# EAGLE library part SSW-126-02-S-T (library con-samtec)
THROUGH-HOLE .025" SQ POST SOCKET Source: Samtec SSW.pdf
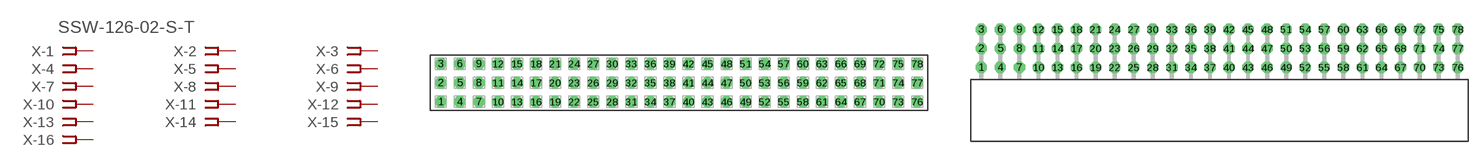
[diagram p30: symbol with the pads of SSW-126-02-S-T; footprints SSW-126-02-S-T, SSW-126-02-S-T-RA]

Designator prefix X; gates -1=FPINV -2=FPIN -3=FPIN -4=FPIN -5=FPIN -6=FPIN -7=FPIN -8=FPIN -9=FPIN -10=FPIN -11=FPIN -12=FPIN -13=FPIN -14=FPIN -15=FPIN -16=FPIN -17=FPIN -18=FPIN -19=FPIN -20=FPIN -21=FPIN -22=FPIN -23=FPIN -24=FPIN -25=FPIN -26=FPIN -27=FPIN -28=FPIN -29=FPIN -30=FPIN -31=FPIN -32=FPIN -33=FPIN -34=FPIN -35=FPIN -36=FPIN -37=FPIN -38=FPIN -39=FPIN -40=FPIN -41=FPIN -42=FPIN -43=FPIN -44=FPIN -45=FPIN -46=FPIN -47=FPIN -48=FPIN -49=FPIN -50=FPIN -51=FPIN -52=FPIN -53=FPIN -54=FPIN -55=FPIN -56=FPIN -57=FPIN -58=FPIN -59=FPIN -60=FPIN -61=FPIN -62=FPIN -63=FPIN -64=FPIN -65=FPIN -66=FPIN -67=FPIN -68=FPIN -69=FPIN -70=FPIN -71=FPIN -72=FPIN -73=FPIN -74=FPIN -75=FPIN -76=FPIN -77=FPIN -78=FPIN

## SSW-126-02-S-T (MPN: SSW-126-02-S-T; OC_FARNELL: unknown; OC_NEWARK: 82P9576)  [SSW-126-02-S-T]
1  -1:1  pas
2  -2:1  pas
3  -3:1  pas
4  -4:1  pas
5  -5:1  pas
6  -6:1  pas
7  -7:1  pas
8  -8:1  pas
9  -9:1  pas
10  -10:1  pas
11  -11:1  pas
12  -12:1  pas
13  -13:1  pas
14  -14:1  pas
15  -15:1  pas
16  -16:1  pas
17  -17:1  pas
18  -18:1  pas
19  -19:1  pas
20  -20:1  pas
21  -21:1  pas
22  -22:1  pas
23  -23:1  pas
24  -24:1  pas
25  -25:1  pas
26  -26:1  pas
27  -27:1  pas
28  -28:1  pas
29  -29:1  pas
30  -30:1  pas
31  -31:1  pas
32  -32:1  pas
33  -33:1  pas
34  -34:1  pas
35  -35:1  pas
36  -36:1  pas
37  -37:1  pas
38  -38:1  pas
39  -39:1  pas
40  -40:1  pas
41  -41:1  pas
42  -42:1  pas
43  -43:1  pas
44  -44:1  pas
45  -45:1  pas
46  -46:1  pas
47  -47:1  pas
48  -48:1  pas
49  -49:1  pas
50  -50:1  pas
51  -51:1  pas
52  -52:1  pas
53  -53:1  pas
54  -54:1  pas
55  -55:1  pas
56  -56:1  pas
57  -57:1  pas
58  -58:1  pas
59  -59:1  pas
60  -60:1  pas
61  -61:1  pas
62  -62:1  pas
63  -63:1  pas
64  -64:1  pas
65  -65:1  pas
66  -66:1  pas
67  -67:1  pas
68  -68:1  pas
69  -69:1  pas
70  -70:1  pas
71  -71:1  pas
72  -72:1  pas
73  -73:1  pas
74  -74:1  pas
75  -75:1  pas
76  -76:1  pas
77  -77:1  pas
78  -78:1  pas

## SSW-126-02-S-TRA (MPN: SSW-126-02-S-T-RA; OC_FARNELL: unknown; OC_NEWARK: 82P9577)  [SSW-126-02-S-T-RA]
Pads as for SSW-126-02-S-T

## Footprint SSW-126-02-S-T (pad centres in mm)
THROUGH-HOLE .025" SQ POST SOCKET Source: Samtec SSW.pdf
drill 1 pad 1.5 octagon: 1 -31.75,-2.54; 2 -31.75,0; 3 -31.75,2.54; 4 -29.21,-2.54; 5 -29.21,0; 6 -29.21,2.54; 7 -26.67,-2.54; 8 -26.67,0; 9 -26.67,2.54; 10 -24.13,-2.54; 11 -24.13,0; 12 -24.13,2.54; 13 -21.59,-2.54; 14 -21.59,0; 15 -21.59,2.54; 16 -19.05,-2.54; 17 -19.05,0; 18 -19.05,2.54; 19 -16.51,-2.54; 20 -16.51,0; 21 -16.51,2.54; 22 -13.97,-2.54; 23 -13.97,0; 24 -13.97,2.54; 25 -11.43,-2.54; 26 -11.43,0; 27 -11.43,2.54; 28 -8.89,-2.54; 29 -8.89,0; 30 -8.89,2.54; 31 -6.35,-2.54; 32 -6.35,0; 33 -6.35,2.54; 34 -3.81,-2.54; 35 -3.81,0; 36 -3.81,2.54; 37 -1.27,-2.54; 38 -1.27,0; 39 -1.27,2.54; 40 1.27,-2.54; 41 1.27,0; 42 1.27,2.54; 43 3.81,-2.54; 44 3.81,0; 45 3.81,2.54; 46 6.35,-2.54; 47 6.35,0; 48 6.35,2.54; 49 8.89,-2.54; 50 8.89,0; 51 8.89,2.54; 52 11.43,-2.54; 53 11.43,0; 54 11.43,2.54; 55 13.97,-2.54; 56 13.97,0; 57 13.97,2.54; 58 16.51,-2.54; 59 16.51,0; 60 16.51,2.54; 61 19.05,-2.54; 62 19.05,0; 63 19.05,2.54; 64 21.59,-2.54; 65 21.59,0; 66 21.59,2.54; 67 24.13,-2.54; 68 24.13,0; 69 24.13,2.54; 70 26.67,-2.54; 71 26.67,0; 72 26.67,2.54; 73 29.21,-2.54; 74 29.21,0; 75 29.21,2.54; 76 31.75,-2.54; 77 31.75,0; 78 31.75,2.54

## Footprint SSW-126-02-S-T-RA (pad centres in mm)
THROUGH-HOLE .025" SQ POST SOCKET Source: Samtec SSW.pdf
drill 1 pad 1.5 octagon: 1 -31.75,1.524; 2 -31.75,4.064; 3 -31.75,6.604; 4 -29.21,1.524; 5 -29.21,4.064; 6 -29.21,6.604; 7 -26.67,1.524; 8 -26.67,4.064; 9 -26.67,6.604; 10 -24.13,1.524; 11 -24.13,4.064; 12 -24.13,6.604; 13 -21.59,1.524; 14 -21.59,4.064; 15 -21.59,6.604; 16 -19.05,1.524; 17 -19.05,4.064; 18 -19.05,6.604; 19 -16.51,1.524; 20 -16.51,4.064; 21 -16.51,6.604; 22 -13.97,1.524; 23 -13.97,4.064; 24 -13.97,6.604; 25 -11.43,1.524; 26 -11.43,4.064; 27 -11.43,6.604; 28 -8.89,1.524; 29 -8.89,4.064; 30 -8.89,6.604; 31 -6.35,1.524; 32 -6.35,4.064; 33 -6.35,6.604; 34 -3.81,1.524; 35 -3.81,4.064; 36 -3.81,6.604; 37 -1.27,1.524; 38 -1.27,4.064; 39 -1.27,6.604; 40 1.27,1.524; 41 1.27,4.064; 42 1.27,6.604; 43 3.81,1.524; 44 3.81,4.064; 45 3.81,6.604; 46 6.35,1.524; 47 6.35,4.064; 48 6.35,6.604; 49 8.89,1.524; 50 8.89,4.064; 51 8.89,6.604; 52 11.43,1.524; 53 11.43,4.064; 54 11.43,6.604; 55 13.97,1.524; 56 13.97,4.064; 57 13.97,6.604; 58 16.51,1.524; 59 16.51,4.064; 60 16.51,6.604; 61 19.05,1.524; 62 19.05,4.064; 63 19.05,6.604; 64 21.59,1.524; 65 21.59,4.064; 66 21.59,6.604; 67 24.13,1.524; 68 24.13,4.064; 69 24.13,6.604; 70 26.67,1.524; 71 26.67,4.064; 72 26.67,6.604; 73 29.21,1.524; 74 29.21,4.064; 75 29.21,6.604; 76 31.75,1.524; 77 31.75,4.064; 78 31.75,6.604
